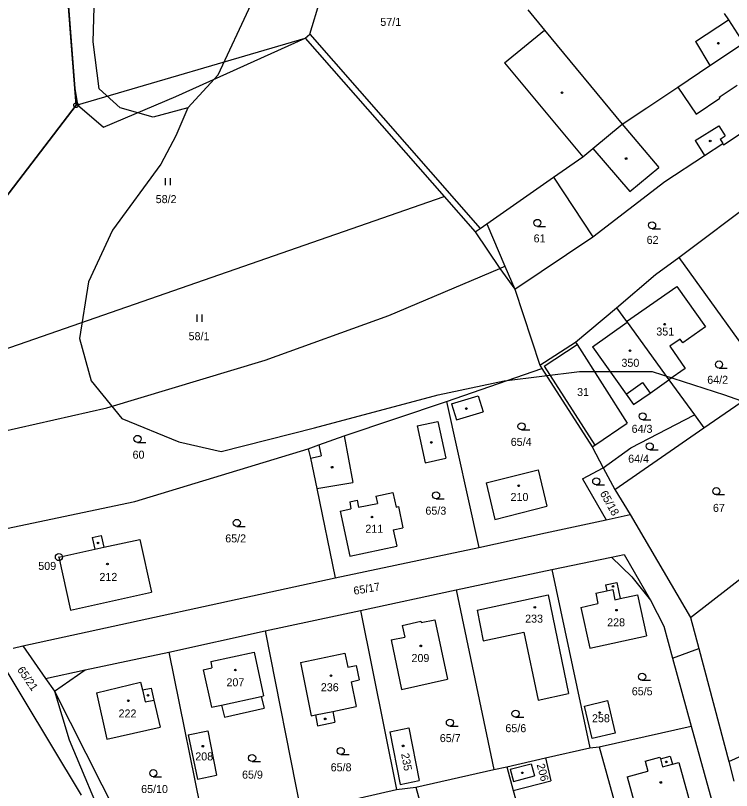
# Model space of a CAD drawing. Extents: x -725765 to -723182, y -1052705 to -1049154.
# Drawn here: x -724971.9 to -724819.8, y -1051081 to -1050916.4 of the extents above; entities that cross this region are included whole.
import ezdxf

# ---------------------------------------------------------------- set-up
doc = ezdxf.new("R2010")
doc.units = 0
for name, color, linetype in [('Vrstva 1', 7, 'Continuous'), ('Vrstva 17', 7, 'Continuous'), ('Vrstva 18', 7, 'Continuous'), ('Vrstva 19', 7, 'Continuous'), ('Vrstva 25', 7, 'Continuous'), ('Vrstva 4', 7, 'Continuous'), ('Vrstva 52', 7, 'Continuous')]:
    doc.layers.add(name, color=color, linetype=linetype)

msp = doc.modelspace()

# ---------------------------------------------------------------- linework, layer by layer
at = {"layer": 'Vrstva 1'}
for points in [[(-724961.29, -1050906.08), (-724959.3, -1050931.91)], [(-724863.09, -1050915.24), (-724859.58, -1050919.5)], [(-724868.07, -1050926.5), (-724859.58, -1050919.5)], [(-724958.69, -1050935.38), (-724910.36, -1050921.21)], [(-724910.36, -1050921.21), (-724880.84, -1050954.87)], [(-724824.41, -1050927.04), (-724817.3, -1050922.28)], [(-724868.07, -1050926.5), (-724851.43, -1050946.43)], [(-724831.24, -1050931.62), (-724824.41, -1050927.04)], [(-724959.3, -1050931.91), (-724959.02, -1050935.48)], [(-724837.81, -1050936.02), (-724831.24, -1050931.62)], [(-724959.02, -1050935.48), (-724992.12, -1050978.69)], [(-724959.02, -1050935.48), (-724958.69, -1050935.38)], [(-724843.05, -1050939.52), (-724837.81, -1050936.02)], [(-724849.26, -1050944.64), (-724843.05, -1050939.52)], [(-724821.51, -1050943.86), (-724816.95, -1050940.84)], [(-724851.43, -1050946.43), (-724849.26, -1050944.64)], [(-724825.54, -1050946.16), (-724821.68, -1050943.61)], [(-724821.68, -1050943.61), (-724821.51, -1050943.86)], [(-724834.02, -1050951.71), (-724825.54, -1050946.16)], [(-724857.64, -1050950.77), (-724851.43, -1050946.43)], [(-724871.79, -1050960.67), (-724857.64, -1050950.77)], [(-724857.64, -1050950.77), (-724849.25, -1050963.43)], [(-724849.25, -1050963.43), (-724834.02, -1050951.71)], [(-724994.29, -1050994.27), (-724880.84, -1050954.87)], [(-724880.84, -1050954.87), (-724874.25, -1050962.39)], [(-724831.02, -1050967.82), (-724814.26, -1050955.21)], [(-724873.18, -1050961.64), (-724871.79, -1050960.67)], [(-724871.79, -1050960.67), (-724867.94, -1050969.68)], [(-724874.25, -1050962.39), (-724873.18, -1050961.64)], [(-724865.88, -1050974.51), (-724849.25, -1050963.43)], [(-724835.97, -1050971.43), (-724831.02, -1050967.82)], [(-724831.02, -1050967.82), (-724811.84, -1050994.44)], [(-724892.59, -1050980.16), (-724869.01, -1050970.13)], [(-724869.01, -1050970.13), (-724867.94, -1050969.68)], [(-724867.94, -1050969.68), (-724865.88, -1050974.51)], [(-724844.24, -1050978.51), (-724835.97, -1050971.43)], [(-724842.15, -1050981.39), (-724831.47, -1050973.95)], [(-724831.47, -1050973.95), (-724825.35, -1050982.56)], [(-724865.88, -1050974.51), (-724860.52, -1050990.72)], [(-724852.95, -1050985.77), (-724844.24, -1050978.51)], [(-724844.24, -1050978.51), (-724842.15, -1050981.39)], [(-724918.87, -1050989.61), (-724892.59, -1050980.16)], [(-724849.38, -1050986.78), (-724842.02, -1050981.55)], [(-724842.15, -1050981.39), (-724842.02, -1050981.55)], [(-724842.02, -1050981.55), (-724833.13, -1050993.79)], [(-724825.35, -1050982.56), (-724830.16, -1050985.96)], [(-724860.52, -1050990.72), (-724852.95, -1050985.77)], [(-724852.95, -1050985.77), (-724852.6, -1050986.32)], [(-724830.73, -1050985.17), (-724832.9, -1050986.67)], [(-724830.16, -1050985.96), (-724830.73, -1050985.17)], [(-724852.6, -1050986.32), (-724841.96, -1051003)], [(-724849.38, -1050986.78), (-724842.22, -1050996.86)], [(-724832.9, -1050986.67), (-724829.65, -1050991.36)], [(-724952.51, -1050999.73), (-724918.87, -1050989.61)], [(-724860.52, -1050990.72), (-724860.11, -1050991.42)], [(-724880.39, -1050998.42), (-724860.11, -1050991.42)], [(-724860.11, -1050991.42), (-724849.43, -1051008)], [(-724829.65, -1050991.36), (-724833.13, -1050993.79)], [(-724837.14, -1050996.62), (-724833.13, -1050993.79)], [(-724833.13, -1050993.79), (-724827.72, -1051001.23)], [(-724842.22, -1050996.86), (-724840.65, -1050999.07)], [(-724840.65, -1050999.07), (-724837.14, -1050996.62)], [(-724902.1, -1051005.69), (-724880.39, -1050998.42)], [(-724880.39, -1050998.42), (-724873.5, -1051029.4)], [(-724825.71, -1051004.02), (-724816.65, -1050997.75)], [(-724993.85, -1051009.11), (-724952.51, -1050999.73)], [(-724841.2, -1051008.25), (-724827.72, -1051001.23)], [(-724827.72, -1051001.23), (-724825.71, -1051004.02)], [(-724848.88, -1051007.65), (-724841.96, -1051003)], [(-724844.64, -1051017.12), (-724825.71, -1051004.02)], [(-724907.5, -1051007.63), (-724902.1, -1051005.69)], [(-724946.57, -1051019.61), (-724909.75, -1051008.44)], [(-724909.75, -1051008.44), (-724907.5, -1051007.63)], [(-724909.75, -1051008.44), (-724909.23, -1051010.41)], [(-724849.43, -1051008), (-724848.88, -1051007.65)], [(-724849.43, -1051008), (-724847.11, -1051012.49)], [(-724847.11, -1051012.49), (-724841.2, -1051008.25)], [(-724909.23, -1051010.41), (-724907.91, -1051016.88)], [(-724871.95, -1051015.7), (-724860.91, -1051012.89)], [(-724860.91, -1051012.89), (-724859.05, -1051020.66)], [(-724851.48, -1051014.82), (-724847.11, -1051012.49)], [(-724847.11, -1051012.49), (-724844.64, -1051017.12)], [(-724828.56, -1051044.26), (-724788.13, -1051012.9)], [(-724851.48, -1051014.82), (-724846.47, -1051023.5)], [(-724907.91, -1051016.88), (-724904.01, -1051035.83)], [(-724871.95, -1051015.7), (-724870.12, -1051023.47)], [(-724895.36, -1051018.49), (-724891.74, -1051017.75)], [(-724895.36, -1051018.49), (-724895.04, -1051020.05)], [(-724891.74, -1051017.75), (-724891.04, -1051020.83)], [(-724844.64, -1051017.12), (-724841.33, -1051022.38)], [(-724985.97, -1051027.89), (-724946.57, -1051019.61)], [(-724900.92, -1051019.69), (-724899.32, -1051019.36)], [(-724900.92, -1051019.69), (-724900.64, -1051021.23)], [(-724899.32, -1051019.36), (-724899.01, -1051020.86)], [(-724899.01, -1051020.86), (-724895.04, -1051020.05)], [(-724902.92, -1051021.71), (-724900.64, -1051021.23)], [(-724902.92, -1051021.71), (-724900.9, -1051031.25)], [(-724891.04, -1051020.83), (-724890.57, -1051020.73)], [(-724890.57, -1051020.73), (-724889.65, -1051025.2)], [(-724870.12, -1051023.47), (-724859.05, -1051020.66)], [(-724859.37, -1051026.32), (-724846.47, -1051023.5)], [(-724846.47, -1051023.5), (-724841.33, -1051022.38)], [(-724841.33, -1051022.38), (-724828.56, -1051044.26)], [(-724891.65, -1051025.65), (-724889.65, -1051025.2)], [(-724955.58, -1051027.3), (-724953.66, -1051026.88)], [(-724953.66, -1051026.88), (-724953.12, -1051029.37)], [(-724891.65, -1051025.65), (-724890.91, -1051029.12)], [(-724873.5, -1051029.4), (-724859.37, -1051026.32)], [(-724955.58, -1051027.3), (-724955.03, -1051029.79)], [(-724953.12, -1051029.37), (-724945.5, -1051027.71)], [(-724945.5, -1051027.71), (-724943.02, -1051038.9)], [(-724962.66, -1051031.45), (-724955.03, -1051029.79)], [(-724904.01, -1051035.83), (-724873.5, -1051029.4)], [(-724900.9, -1051031.25), (-724890.91, -1051029.12)], [(-724962.66, -1051031.45), (-724960.22, -1051042.69)], [(-724857.98, -1051034.08), (-724845.34, -1051031.45)], [(-724845.34, -1051031.45), (-724842.61, -1051030.87)], [(-724842.61, -1051030.87), (-724837.05, -1051040.61)], [(-724878.32, -1051038.42), (-724857.98, -1051034.08)], [(-724857.98, -1051034.08), (-724849.89, -1051071.93)], [(-724970.31, -1051050.31), (-724904.01, -1051035.83)], [(-724898.62, -1051042.8), (-724878.32, -1051038.42)], [(-724878.32, -1051038.42), (-724870.3, -1051076.59)], [(-724846.58, -1051037.35), (-724844.2, -1051036.84)], [(-724846.58, -1051037.35), (-724846.31, -1051038.62)], [(-724844.2, -1051036.84), (-724843.46, -1051040.26)], [(-724960.22, -1051042.69), (-724943.02, -1051038.9)], [(-724873.86, -1051042.71), (-724858.77, -1051039.45)], [(-724858.77, -1051039.45), (-724854.46, -1051060.43)], [(-724848.64, -1051039.13), (-724846.31, -1051038.62)], [(-724848.64, -1051039.13), (-724848.2, -1051041.31)], [(-724843.46, -1051040.26), (-724839.82, -1051039.47)], [(-724839.82, -1051039.47), (-724837.92, -1051048.14)], [(-724851.86, -1051042.12), (-724848.2, -1051041.31)], [(-724837.05, -1051040.61), (-724834.24, -1051046.14)], [(-724820.41, -1051074.88), (-724745.23, -1051041)], [(-724918.87, -1051047.1), (-724898.62, -1051042.8)], [(-724898.62, -1051042.8), (-724890.95, -1051080.83)], [(-724873.86, -1051042.71), (-724872.58, -1051049.22)], [(-724851.86, -1051042.12), (-724849.95, -1051050.77)], [(-724885.75, -1051045.37), (-724882.87, -1051044.74)], [(-724882.87, -1051044.74), (-724880.12, -1051057.36)], [(-724828.56, -1051044.26), (-724826.8, -1051050.88)], [(-724889.75, -1051045.99), (-724885.78, -1051045.08)], [(-724889.75, -1051045.99), (-724889.23, -1051048.43)], [(-724885.78, -1051045.08), (-724885.75, -1051045.37)], [(-724834.24, -1051046.14), (-724832.38, -1051052.9)], [(-724939.3, -1051051.63), (-724918.87, -1051047.1)], [(-724918.87, -1051047.1), (-724911.27, -1051085.47)], [(-724872.58, -1051049.22), (-724863.96, -1051047.4)], [(-724863.96, -1051047.4), (-724860.9, -1051061.86)], [(-724849.95, -1051050.77), (-724837.92, -1051048.14)], [(-724892.13, -1051049.05), (-724889.23, -1051048.43)], [(-724892.13, -1051049.05), (-724889.88, -1051059.55)], [(-724976.27, -1051051.61), (-724964.46, -1051071.2)], [(-724972.36, -1051050.76), (-724970.31, -1051050.31)], [(-724970.31, -1051050.31), (-724965.5, -1051057.22)], [(-724957.08, -1051055.42), (-724939.3, -1051051.63)], [(-724939.3, -1051051.63), (-724931.61, -1051089.72)], [(-724832.38, -1051052.9), (-724826.8, -1051050.88)], [(-724826.8, -1051050.88), (-724820.41, -1051074.88)], [(-724930.43, -1051053.64), (-724921.17, -1051051.66)], [(-724921.17, -1051051.66), (-724919.19, -1051060.92)], [(-724911.39, -1051053.86), (-724901.92, -1051051.86)], [(-724901.92, -1051051.86), (-724901.29, -1051054.82)], [(-724832.38, -1051052.9), (-724828.41, -1051067.33)], [(-724930.43, -1051053.64), (-724930.17, -1051054.97)], [(-724911.39, -1051053.86), (-724909.13, -1051065.16)], [(-724901.29, -1051054.82), (-724899.51, -1051054.49)], [(-724899.51, -1051054.49), (-724898.9, -1051057.55)], [(-724965.5, -1051057.22), (-724957.08, -1051055.42)], [(-724932.01, -1051055.38), (-724930.17, -1051054.97)], [(-724932.01, -1051055.38), (-724930.24, -1051063.34)], [(-724965.5, -1051057.22), (-724963.58, -1051059.89)], [(-724954.7, -1051060.28), (-724945.32, -1051058.02)], [(-724945.32, -1051058.02), (-724944.92, -1051059.67)], [(-724900.62, -1051057.96), (-724898.9, -1051057.55)], [(-724900.62, -1051057.96), (-724899.55, -1051063.2)], [(-724889.88, -1051059.55), (-724880.12, -1051057.36)], [(-724944.92, -1051059.67), (-724943.06, -1051059.31)], [(-724943.06, -1051059.31), (-724942.48, -1051061.81)], [(-724963.58, -1051059.89), (-724960.47, -1051070.23)], [(-724963.58, -1051059.89), (-724946.87, -1051092.99)], [(-724954.7, -1051060.28), (-724952.48, -1051070.12)], [(-724928.12, -1051062.88), (-724919.68, -1051061.03)], [(-724919.68, -1051061.03), (-724919.19, -1051060.92)], [(-724860.9, -1051061.86), (-724854.46, -1051060.43)], [(-724942.48, -1051061.81), (-724941.14, -1051067.54)], [(-724930.24, -1051063.34), (-724928.12, -1051062.88)], [(-724851.08, -1051063.08), (-724846.18, -1051061.93)], [(-724849.46, -1051069.97), (-724851.08, -1051063.08)], [(-724846.18, -1051061.93), (-724844.56, -1051068.82)], [(-724904.47, -1051064.21), (-724899.55, -1051063.2)], [(-724904.47, -1051064.21), (-724904.07, -1051066.52)], [(-724909.13, -1051065.16), (-724908.19, -1051064.97)], [(-724908.19, -1051064.97), (-724907.74, -1051067.27)], [(-724952.48, -1051070.12), (-724941.14, -1051067.54)], [(-724907.74, -1051067.27), (-724904.07, -1051066.52)], [(-724892.4, -1051068.58), (-724888.38, -1051067.7)], [(-724888.38, -1051067.7), (-724886.16, -1051078.92)], [(-724847.95, -1051071.78), (-724828.41, -1051067.33)], [(-724828.41, -1051067.33), (-724824.72, -1051080.67)], [(-724935.18, -1051069.17), (-724931.06, -1051068.34)], [(-724935.18, -1051069.17), (-724933.26, -1051078.61)], [(-724931.06, -1051068.34), (-724929.17, -1051077.78)], [(-724892.4, -1051068.58), (-724890.2, -1051079.72)], [(-724844.56, -1051068.82), (-724849.46, -1051069.97)], [(-724964.46, -1051071.2), (-724957.95, -1051081.99)], [(-724960.47, -1051070.23), (-724952.37, -1051089.69)], [(-724859.33, -1051074.09), (-724849.89, -1051071.93)], [(-724849.89, -1051071.93), (-724847.95, -1051071.78)], [(-724847.95, -1051071.78), (-724837.23, -1051110.34)], [(-724867.58, -1051075.97), (-724859.33, -1051074.09)], [(-724859.33, -1051074.09), (-724858.22, -1051078.97)], [(-724838.15, -1051074.79), (-724835.05, -1051073.91)], [(-724835.05, -1051073.91), (-724834.95, -1051074.27)], [(-724834.95, -1051074.27), (-724832.87, -1051073.7)], [(-724832.87, -1051073.7), (-724832.39, -1051075.44)], [(-724870.3, -1051076.59), (-724867.58, -1051075.97)], [(-724867.58, -1051075.97), (-724866.18, -1051080.99)], [(-724838.15, -1051074.79), (-724837.62, -1051076.9)], [(-724832.39, -1051075.44), (-724831.04, -1051075.08)], [(-724831.04, -1051075.08), (-724828.29, -1051085.04)], [(-724820.41, -1051074.88), (-724819.35, -1051079.05)], [(-724933.26, -1051078.61), (-724929.17, -1051077.78)], [(-724886.87, -1051080.34), (-724870.3, -1051076.59)], [(-724842.01, -1051078.13), (-724837.62, -1051076.9)], [(-724890.2, -1051079.72), (-724886.16, -1051078.92)], [(-724866.18, -1051080.99), (-724858.22, -1051078.97)], [(-724842.01, -1051078.13), (-724839.24, -1051088.1)], [(-724906.4, -1051084.35), (-724890.95, -1051080.83)], [(-724890.95, -1051080.83), (-724886.87, -1051080.34)], [(-724886.87, -1051080.34), (-724876.24, -1051118.93)], [(-724866.18, -1051080.99), (-724856.76, -1051114.67)], [(-724824.72, -1051080.67), (-724817.68, -1051106.09)]]:
    msp.add_lwpolyline(points, dxfattribs=at)
at = {"layer": 'Vrstva 25'}
for points in [[(-724940.02, -1050952.45), (-724940.02, -1050950.95)], [(-724938.98, -1050952.45), (-724938.98, -1050950.95)], [(-724861.06, -1050961.22), (-724859.31, -1050961.22)], [(-724836.7, -1050961.72), (-724834.95, -1050961.72)], [(-724933.29, -1050981.45), (-724933.29, -1050979.95)], [(-724932.25, -1050981.45), (-724932.25, -1050979.95)], [(-724822.49, -1050991.29), (-724820.74, -1050991.29)], [(-724838.69, -1051002.29), (-724836.94, -1051002.29)], [(-724864.43, -1051004.43), (-724862.68, -1051004.43)], [(-724945.97, -1051007.1), (-724944.22, -1051007.1)], [(-724837.19, -1051008.66), (-724835.44, -1051008.66)], [(-724848.57, -1051016.1), (-724846.82, -1051016.1)], [(-724823.06, -1051018.18), (-724821.31, -1051018.18)], [(-724882.57, -1051019.08), (-724880.82, -1051019.08)], [(-724924.88, -1051024.94), (-724923.13, -1051024.94)], [(-724838.81, -1051057.62), (-724837.06, -1051057.62)], [(-724865.7, -1051065.46), (-724863.95, -1051065.46)], [(-724879.64, -1051067.36), (-724877.89, -1051067.36)], [(-724902.81, -1051073.39), (-724901.06, -1051073.39)], [(-724921.63, -1051074.87), (-724919.88, -1051074.87)], [(-724942.62, -1051078.09), (-724940.87, -1051078.09)]]:
    msp.add_lwpolyline(points, dxfattribs=at)
for centre, radius in [((-724822.63, -1050922.3), 0.175), ((-724855.83, -1050932.82), 0.175), ((-724959.02, -1050935.48), 0.5), ((-724959.02, -1050935.48), 0.032), ((-724824.36, -1050943.06), 0.175), ((-724842.22, -1050946.8), 0.175), ((-724861.06, -1050960.47), 0.75), ((-724836.7, -1050960.97), 0.75), ((-724834.02, -1050981.99), 0.175), ((-724841.39, -1050987.62), 0.175), ((-724822.49, -1050990.54), 0.75), ((-724876.13, -1050999.9), 0.175), ((-724838.69, -1051001.54), 0.75), ((-724864.43, -1051003.68), 0.75), ((-724945.97, -1051006.35), 0.75), ((-724883.59, -1051007.1), 0.175), ((-724837.19, -1051007.91), 0.75), ((-724904.65, -1051012.36), 0.175), ((-724848.57, -1051015.35), 0.75), ((-724865.02, -1051016.3), 0.175), ((-724823.06, -1051017.43), 0.75), ((-724882.57, -1051018.33), 0.75), ((-724924.88, -1051024.19), 0.75), ((-724896.18, -1051022.95), 0.175), ((-724954.35, -1051028.45), 0.175), ((-724962.66, -1051031.45), 0.75), ((-724962.66, -1051031.45), 0.032), ((-724952.36, -1051032.93), 0.175), ((-724845.02, -1051037.69), 0.175), ((-724861.6, -1051042.11), 0.175), ((-724844.26, -1051042.72), 0.175), ((-724885.82, -1051050.3), 0.175), ((-724925.19, -1051055.43), 0.175), ((-724904.89, -1051056.65), 0.175), ((-724838.81, -1051056.87), 0.75), ((-724943.76, -1051060.8), 0.175), ((-724947.93, -1051061.97), 0.175), ((-724865.7, -1051064.71), 0.75), ((-724847.85, -1051064.49), 0.175), ((-724906.11, -1051065.81), 0.175), ((-724879.64, -1051066.61), 0.75), ((-724889.57, -1051071.54), 0.175), ((-724932.1, -1051071.61), 0.175), ((-724902.81, -1051072.64), 0.75), ((-724921.63, -1051074.12), 0.75), ((-724833.68, -1051074.95), 0.175), ((-724942.62, -1051077.34), 0.75), ((-724864.24, -1051077.27), 0.175), ((-724834.86, -1051079.32), 0.175)]:
    msp.add_circle(centre, radius, dxfattribs=at)
at = {"layer": 'Vrstva 4'}
for points in [[(-724909.38, -1050920.35), (-724905.02, -1050905.87)], [(-724821.4, -1050916), (-724820.51, -1050917.36)], [(-724827.51, -1050921.91), (-724820.51, -1050917.36)], [(-724820.51, -1050917.36), (-724817.3, -1050922.28)], [(-724859.58, -1050919.5), (-724843.05, -1050939.52)], [(-724937.84, -1050933.61), (-724910.36, -1050921.21)], [(-724910.36, -1050921.21), (-724909.38, -1050920.35)], [(-724909.38, -1050920.35), (-724873.18, -1050961.64)], [(-724827.51, -1050921.91), (-724824.41, -1050927.04)], [(-724822.44, -1050933.75), (-724818.66, -1050931.23)], [(-724959.3, -1050931.91), (-724958.69, -1050935.38)], [(-724831.24, -1050931.62), (-724827.31, -1050937.37)], [(-724953.17, -1050940.12), (-724937.84, -1050933.61)], [(-724827.31, -1050937.37), (-724822.29, -1050933.98)], [(-724822.44, -1050933.75), (-724822.29, -1050933.98)], [(-724958.69, -1050935.38), (-724953.17, -1050940.12)], [(-724843.05, -1050939.52), (-724835.25, -1050948.69)], [(-724827.52, -1050942.94), (-724822.55, -1050939.86)], [(-724822.55, -1050939.86), (-724821.15, -1050941.99)], [(-724827.52, -1050942.94), (-724825.54, -1050946.16)], [(-724822.27, -1050942.71), (-724821.15, -1050941.99)], [(-724822.27, -1050942.71), (-724821.68, -1050943.61)], [(-724849.26, -1050944.64), (-724841.42, -1050953.81)], [(-724841.42, -1050953.81), (-724835.25, -1050948.69)], [(-724874.25, -1050962.39), (-724869.01, -1050970.13)], [(-724869.01, -1050970.13), (-724865.88, -1050974.51)], [(-724859.65, -1050990.93), (-724852.6, -1050986.32)], [(-724859.65, -1050990.93), (-724848.88, -1051007.65)], [(-724842.22, -1050996.86), (-724838.72, -1050994.38)], [(-724838.72, -1050994.38), (-724837.14, -1050996.62)], [(-724879.27, -1050998.89), (-724873.61, -1050997.2)], [(-724873.61, -1050997.2), (-724872.56, -1051000.58)], [(-724879.27, -1050998.89), (-724878.23, -1051002.28)], [(-724878.23, -1051002.28), (-724872.56, -1051000.58)], [(-724886.61, -1051003.59), (-724882.21, -1051002.63)], [(-724886.61, -1051003.59), (-724884.9, -1051011.42)], [(-724882.21, -1051002.63), (-724880.49, -1051010.45)], [(-724902.1, -1051005.69), (-724900.24, -1051015.64)], [(-724907.5, -1051007.63), (-724906.98, -1051009.95)], [(-724909.23, -1051010.41), (-724906.98, -1051009.95)], [(-724884.9, -1051011.42), (-724880.49, -1051010.45)], [(-724907.91, -1051016.88), (-724900.24, -1051015.64)], [(-724955.03, -1051029.79), (-724953.12, -1051029.37)], [(-724845.34, -1051031.45), (-724841.02, -1051035.61)], [(-724841.02, -1051035.61), (-724837.05, -1051040.61)], [(-724846.31, -1051038.62), (-724845.06, -1051038.35)], [(-724845.06, -1051038.35), (-724844.59, -1051040.51)], [(-724844.59, -1051040.51), (-724843.46, -1051040.26)], [(-724963.58, -1051059.89), (-724957.08, -1051055.42)], [(-724944.92, -1051059.67), (-724944.32, -1051062.16)], [(-724919.68, -1051061.03), (-724919.11, -1051063.54)], [(-724944.32, -1051062.16), (-724942.48, -1051061.81)], [(-724928.12, -1051062.88), (-724927.5, -1051065.48)], [(-724927.5, -1051065.48), (-724919.11, -1051063.54)], [(-724908.19, -1051064.97), (-724904.47, -1051064.21)], [(-724834.95, -1051074.27), (-724834.47, -1051076)], [(-724866.81, -1051076.49), (-724862.39, -1051075.33)], [(-724862.39, -1051075.33), (-724861.67, -1051077.94)], [(-724834.47, -1051076), (-724832.39, -1051075.44)], [(-724866.81, -1051076.49), (-724866.14, -1051079.09)], [(-724866.14, -1051079.09), (-724861.67, -1051077.94)]]:
    msp.add_lwpolyline(points, dxfattribs=at)
at = {"layer": 'Vrstva 52'}
for points in [[(-724935.31, -1050936), (-724928.81, -1050929), (-724921.81, -1050914), (-724914.81, -1050892), (-724908.69, -1050863), (-724905.5, -1050842), (-724893.88, -1050794), (-724875.69, -1050728), (-724864.81, -1050699), (-724857.19, -1050685), (-724844.38, -1050668), (-724831.88, -1050654), (-724822.88, -1050647), (-724816.5, -1050644), (-724814.99, -1050644), (-724813.33, -1050644)], [(-725040.9, -1050880.49), (-725031.43, -1050908.84), (-724999.85, -1050999.45), (-724994.58, -1050998.09), (-724994.29, -1050994.27), (-724993.62, -1050987.89), (-724992.12, -1050978.69), (-724959.02, -1050935.48), (-724959.3, -1050931.91), (-724960.13, -1050921.08), (-724961.29, -1050906.08), (-724961.46, -1050903.95), (-724954.82, -1050902.24)], [(-724935.31, -1050936), (-724942.63, -1050938), (-724949.63, -1050936), (-724954.13, -1050932), (-724955.38, -1050922), (-724954.82, -1050902.24)], [(-724935.31, -1050936), (-724937.81, -1050942), (-724941, -1050948), (-724951.31, -1050962), (-724956.38, -1050973), (-724958.31, -1050985), (-724955.81, -1050994), (-724949.31, -1051002), (-724937.19, -1051007), (-724928.19, -1051009), (-724908.38, -1051004), (-724882.13, -1050997), (-724868.13, -1050994), (-724852.13, -1050992), (-724836.69, -1050992), (-724821.31, -1050997), (-724801.5, -1051004)]]:
    msp.add_lwpolyline(points, dxfattribs=at)

# ---------------------------------------------------------------- texts
at = {"layer": 'Vrstva 17'}
msp.add_text('509', height=1.7, dxfattribs=at).set_placement((-724967.04, -1051034.17))
at = {"layer": 'Vrstva 18'}
for s, p in [('57/1', (-724894.41, -1050918.63)), ('58/2', (-724942.11, -1050956.27)), ('61', (-724861.86, -1050964.61)), ('62', (-724837.86, -1050964.93)), ('58/1', (-724935.12, -1050985.38)), ('64/2', (-724824.99, -1050994.64)), ('64/3', (-724841.05, -1051005.06)), ('65/4', (-724866.72, -1051007.83)), ('60', (-724947.02, -1051010.55)), ('64/4', (-724841.78, -1051011.4)), ('67', (-724823.78, -1051021.85)), ('65/3', (-724884.83, -1051022.44)), ('65/2', (-724927.34, -1051028.33)), ('65/5', (-724841.01, -1051060.8)), ('65/6', (-724867.85, -1051068.64)), ('65/7', (-724881.78, -1051070.74)), ('65/8', (-724904.95, -1051076.94)), ('65/9', (-724923.77, -1051078.5)), ('65/10', (-724945.2, -1051081.56))]:
    msp.add_text(s, height=1.7, dxfattribs=at).set_placement(p)
for s, rotation, p in [('65/18', 299.2024, (-724847.85, -1051017.9)), ('65/17', 10.0001, (-724899.96, -1051039.48)), ('65/21', 304.7024, (-724971.6, -1051055.39))]:
    msp.add_text(s, height=1.7, rotation=rotation, dxfattribs=at).set_placement(p)
at = {"layer": 'Vrstva 19'}
for s, p in [('351', (-724835.8, -1050984.39)), ('350', (-724843.21, -1050991.03)), ('31', (-724852.63, -1050997.24)), ('210', (-724866.76, -1051019.53)), ('211', (-724897.59, -1051026.27)), ('212', (-724954.06, -1051036.51)), ('233', (-724863.66, -1051045.37)), ('228', (-724846.24, -1051046.15)), ('209', (-724887.79, -1051053.74)), ('207', (-724927.08, -1051058.89)), ('236', (-724907.04, -1051059.94)), ('222', (-724949.99, -1051065.51)), ('258', (-724849.46, -1051066.52)), ('208', (-724933.7, -1051074.63))]:
    msp.add_text(s, height=1.7, dxfattribs=at).set_placement(p)
for s, rotation, p in [('235', 280.1022, (-724890, -1051073.23)), ('206', 285.1023, (-724861.23, -1051075.55))]:
    msp.add_text(s, height=1.7, rotation=rotation, dxfattribs=at).set_placement(p)

doc.saveas('drawing.dxf')
